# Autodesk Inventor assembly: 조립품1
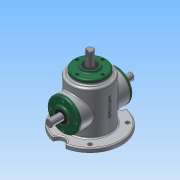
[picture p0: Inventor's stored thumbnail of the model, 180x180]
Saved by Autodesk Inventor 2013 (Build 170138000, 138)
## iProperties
Created: 2018-04
Part Number: 조립품1
Document SubType Name: Assembly
Designer: Administrator
Author: Administrator
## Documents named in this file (14)
- C:\Users\Administrator\Desktop\480408V1006\조립품1.iam
- C:\Users\Administrator\Desktop\480408V1006\본체.ipt
- C:\Users\Administrator\Desktop\480408V1006\메인 축.ipt
- 메인 축.ipt
- C:\Users\Administrator\Desktop\480408V1006\서브 축.ipt
- 서브 축.ipt
- C:\Users\Administrator\Desktop\480408V1006\커버.ipt
- C:\Users\Administrator\Desktop\480408V1006\베어링 6203.ipt
- C:\Users\Administrator\Desktop\480408V1006\오일 실.ipt
- 오일 실.ipt
- C:\Users\Administrator\Desktop\480408V1006\키 5x5.ipt
- C:\Users\Administrator\Desktop\480408V1006\키 4x4.ipt
- C:\Users\Administrator\Desktop\480408V1006\메인 베벨기어.ipt
- C:\Users\Administrator\Desktop\480408V1006\서브 베벨기어.ipt
